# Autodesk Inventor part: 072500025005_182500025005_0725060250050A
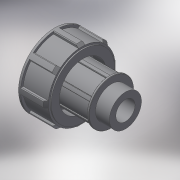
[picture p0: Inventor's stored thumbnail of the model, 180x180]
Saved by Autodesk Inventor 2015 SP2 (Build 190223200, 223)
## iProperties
Created: 2017-04
Part Number: 072500025005_182500025005_0725060250050A
Material: Generic
Description: PLASSON THREADED ADAPTOR 25-1/2"
Document SubType Name: Modeling
Designer: KIM
Density: 1 g/cm^3
Appearance: Default
Author: KIM
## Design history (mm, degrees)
derived "07250.ipt"
feature "Solid1::07250.ipt"
tag "TaggingFeature1"
body "Solid1"
other parameters: "d1" = 20.955, "d2" = 79, "d3" = 17, "d6" = 54, "d7" = 50.22, "d8" = 43.2, "d9" = 25, "d10" = 29.337, "d12" = 12.573, "d13" = 16.764, "d14" = 19.55, "d15" = 40.5, "d16" = 2.37, "d17" = 31.6, "d18" = 17, "d19" = 20.4, "d24" = 4.191, "d25" = 2.0955, "d27" = 0, "d28" = 1.6764, "d31" = 0.4191, "d35" = 360 deg, "d41" = 29.337, "d56" = 27.5, "d57" = 2.5, "d58" = 1.25, "d60" = 0, "d61" = 0.20955, "d64" = 0.20955, "d68" = 360 deg, "d_" = 25, "R_" = 20.955, "E_" = 54, "H_" = 79, "l_2" = 17, "d55" = 25
